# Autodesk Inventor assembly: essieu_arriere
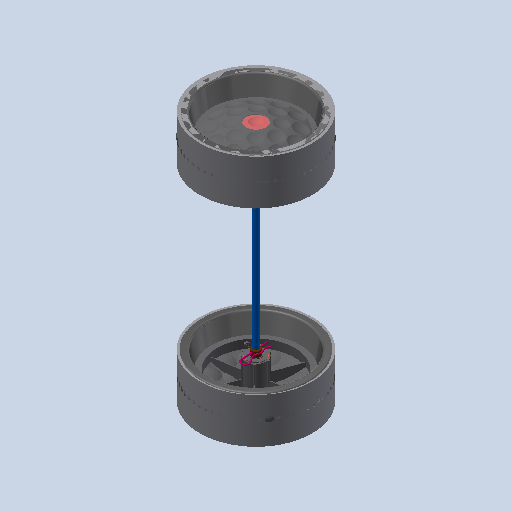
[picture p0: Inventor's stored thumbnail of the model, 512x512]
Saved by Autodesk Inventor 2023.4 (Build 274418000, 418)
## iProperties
Created: 2011-01
Part Number: essieu_arriere
Document SubType Name: Assembly
Designer: eric
Mass: 6204.37 g
Surface Area: 10780.2 cm^2
Volume: 6204.37 cm^3
Density: 1 g/cm^3
Author: eric
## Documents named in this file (5)
- C:\Users\bruno\Documents\1-Cours-2024-25\TSsI\7-Dynamique\chariot de golf\chariot_de_golf\chariot_de_golf_trolem\essieu_arriere.iam
- C:\Users\bruno\Documents\1-Cours-2024-25\TSsI\7-Dynamique\chariot de golf\chariot_de_golf\chariot_de_golf_trolem\62goupille_epingle_Defaut.ipt
- C:\Users\bruno\Documents\1-Cours-2024-25\TSsI\7-Dynamique\chariot de golf\chariot_de_golf\chariot_de_golf_trolem\montage7roue_caoutchouc_Defaut.iam
- C:\Users\bruno\Documents\1-Cours-2024-25\TSsI\7-Dynamique\chariot de golf\chariot_de_golf\chariot_de_golf_trolem\51axe_Defaut.ipt
- C:\Users\bruno\Documents\1-Cours-2024-25\TSsI\7-Dynamique\chariot de golf\chariot_de_golf\chariot_de_golf_trolem\12roue+axe_Defaut.iam
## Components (5 placed, 4 different names)
1. 12roue+axe_Defaut:1 [sub-assembly]
2. montage7roue_caoutchouc_Defaut:1 [sub-assembly]
3. montage7roue_caoutchouc_Defaut:2 [sub-assembly]
4. 51axe_Defaut:1
5. 62goupille_epingle_Defaut:1
